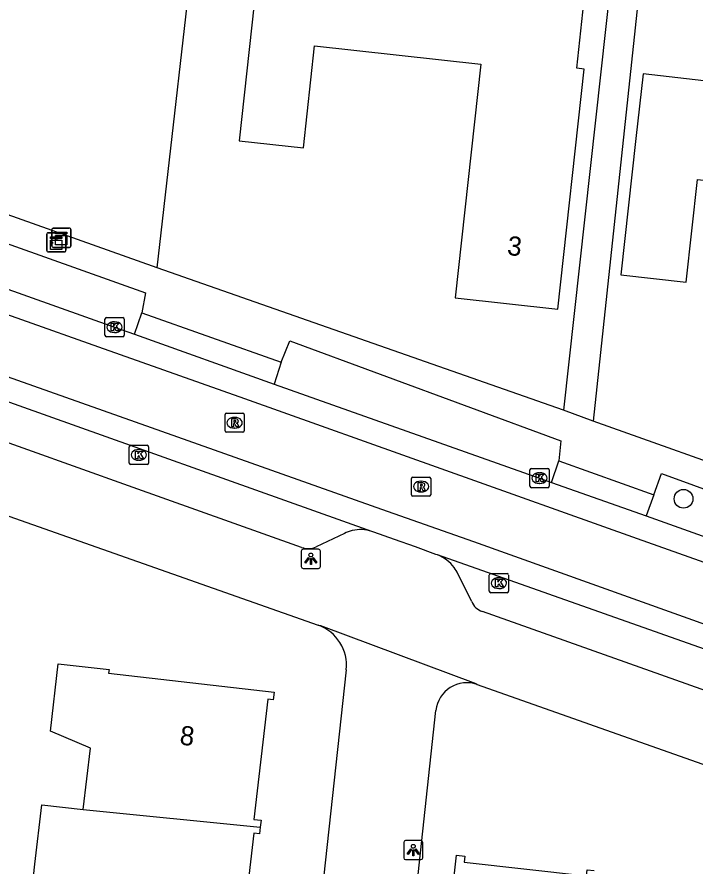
# Model space of a CAD drawing. Extents: x 162398 to 163643, y 386453 to 387397.
# Drawn here: x 162580.44 to 162615.85, y 386600.89 to 386645.28 of the extents above; entities that cross this region are included whole.
import ezdxf

# ---------------------------------------------------------------- set-up
doc = ezdxf.new("R2010")
doc.units = 0
for name, color, linetype in [('IMGEO_Boom', 7, 'Continuous'), ('IMGEO_Groenvoorziening', 7, 'Continuous'), ('IMGEO_Kast', 7, 'Continuous'), ('IMGEO_Kolk', 7, 'Continuous'), ('IMGEO_Lichtpunt', 7, 'Continuous'), ('IMGEO_Pand', 7, 'Continuous'), ('IMGEO_Pand_nummerreeks', 7, 'Continuous'), ('IMGEO_Rijbaan_lokaal_gesloten', 7, 'Continuous'), ('IMGEO_Rioolput', 7, 'Continuous'), ('IMGEO_Voetpad_open', 7, 'Continuous')]:
    doc.layers.add(name, color=color, linetype=linetype)

msp = doc.modelspace()

# ---------------------------------------------------------------- linework, layer by layer
at = {"layer": 'IMGEO_Boom'}
msp.add_circle((162615.249, 386620.12), 0.489, dxfattribs=at)
at = {"layer": 'IMGEO_Groenvoorziening'}
msp.add_lwpolyline([(162587.764, 386632.176), (162589.976, 386651.544)], dxfattribs=at)
at = {"layer": 'IMGEO_Kast'}
for p, q in [((162582.331, 386634.248), (162583.172, 386634.248)), ((162583.172, 386634.248), (162582.331, 386634.248)), ((162581.996, 386633.09), (162581.996, 386633.931)), ((162581.996, 386633.931), (162581.996, 386633.09)), ((162582.071, 386634.015), (162582.912, 386634.015)), ((162582.912, 386634.015), (162582.071, 386634.015)), ((162582.256, 386633.323), (162582.256, 386634.164)), ((162582.256, 386634.164), (162582.256, 386633.323)), ((162582.996, 386633.94), (162582.996, 386633.099)), ((162582.996, 386633.099), (162582.996, 386633.94)), ((162583.256, 386634.173), (162583.256, 386633.332)), ((162583.256, 386633.332), (162583.256, 386634.173)), ((162582.921, 386633.015), (162582.08, 386633.015)), ((162582.08, 386633.015), (162582.921, 386633.015)), ((162583.181, 386633.248), (162582.34, 386633.248)), ((162582.34, 386633.248), (162583.181, 386633.248))]:
    msp.add_line(p, q, dxfattribs=at)
for points in [[(162582.191, 386633.805), (162582.791, 386633.805), (162582.791, 386633.72), (162582.191, 386633.72), (162582.191, 386633.805)], [(162582.451, 386634.038), (162583.051, 386634.038), (162583.051, 386633.953), (162582.451, 386633.953), (162582.451, 386634.038)], [(162582.451, 386633.863), (162583.051, 386633.863), (162583.051, 386633.374), (162582.451, 386633.374), (162582.451, 386633.863)], [(162582.191, 386633.63), (162582.791, 386633.63), (162582.791, 386633.141), (162582.191, 386633.141), (162582.191, 386633.63)]]:
    msp.add_lwpolyline(points, dxfattribs=at)
for centre in [(162582.275, 386633.479), (162582.535, 386633.712)]:
    msp.add_circle(centre, 0.0377, dxfattribs=at)
for centre, start, end in [((162582.334, 386634.17), 92.4484, 184.2845), ((162582.334, 386634.17), 92.4484, 184.2845), ((162583.178, 386634.17), 2.4484, 94.2845), ((162583.178, 386634.17), 2.4484, 94.2845), ((162582.074, 386633.937), 92.4484, 184.2845), ((162582.074, 386633.937), 92.4484, 184.2845), ((162582.918, 386633.937), 2.4484, 94.2845), ((162582.918, 386633.937), 2.4484, 94.2845), ((162582.334, 386633.326), 182.4484, 274.2845), ((162582.334, 386633.326), 182.4484, 274.2845), ((162583.178, 386633.326), 272.4484, 4.2845), ((162583.178, 386633.326), 272.4484, 4.2845), ((162582.074, 386633.093), 182.4484, 274.2845), ((162582.074, 386633.093), 182.4484, 274.2845), ((162582.918, 386633.093), 272.4484, 4.2845), ((162582.918, 386633.093), 272.4484, 4.2845)]:
    msp.add_arc(centre, 0.0779, start, end, dxfattribs=at)
at = {"layer": 'IMGEO_Kolk'}
for p, q in [((162585.034, 386628.656), (162585.034, 386629.508)), ((162585.109, 386629.582), (162585.961, 386629.582)), ((162585.522, 386629.362), (162585.547, 386629.362)), ((162586.035, 386629.508), (162586.035, 386628.656)), ((162585.961, 386628.582), (162585.109, 386628.582)), ((162585.545, 386628.802), (162585.52, 386628.802)), ((162586.305, 386621.986), (162586.305, 386622.838)), ((162586.38, 386622.912), (162587.232, 386622.912)), ((162586.793, 386622.692), (162586.818, 386622.692)), ((162587.306, 386622.838), (162587.306, 386621.986)), ((162587.232, 386621.912), (162586.38, 386621.912)), ((162586.816, 386622.132), (162586.791, 386622.132)), ((162607.229, 386620.773), (162607.229, 386621.625)), ((162607.304, 386621.699), (162608.156, 386621.699)), ((162607.717, 386621.479), (162607.742, 386621.479)), ((162608.23, 386621.625), (162608.23, 386620.773)), ((162607.74, 386620.919), (162607.715, 386620.919)), ((162608.156, 386620.699), (162607.304, 386620.699)), ((162605.107, 386615.289), (162605.107, 386616.141)), ((162605.182, 386616.215), (162606.034, 386616.215)), ((162606.108, 386616.141), (162606.108, 386615.289)), ((162605.595, 386615.995), (162605.62, 386615.995)), ((162606.034, 386615.215), (162605.182, 386615.215)), ((162605.618, 386615.435), (162605.593, 386615.435))]:
    msp.add_line(p, q, dxfattribs=at)
for points in [[(162585.034, 386628.656), (162585.034, 386629.508)], [(162585.109, 386629.582), (162585.961, 386629.582)], [(162586.035, 386629.508), (162586.035, 386628.656)], [(162585.355, 386629.282), (162585.478, 386629.282), (162585.478, 386629.131), (162585.608, 386629.282), (162585.772, 386629.282), (162585.626, 386629.131), (162585.779, 386628.882), (162585.627, 386628.882), (162585.542, 386629.046), (162585.478, 386628.979), (162585.478, 386628.882), (162585.355, 386628.882), (162585.355, 386629.282)], [(162585.961, 386628.582), (162585.109, 386628.582)], [(162586.305, 386621.986), (162586.305, 386622.838)], [(162586.38, 386622.912), (162587.232, 386622.912)], [(162587.306, 386622.838), (162587.306, 386621.986)], [(162586.626, 386622.612), (162586.749, 386622.612), (162586.749, 386622.461), (162586.879, 386622.612), (162587.043, 386622.612), (162586.897, 386622.461), (162587.05, 386622.212), (162586.898, 386622.212), (162586.813, 386622.376), (162586.749, 386622.309), (162586.749, 386622.212), (162586.626, 386622.212), (162586.626, 386622.612)], [(162587.232, 386621.912), (162586.38, 386621.912)], [(162607.229, 386620.773), (162607.229, 386621.625)], [(162607.304, 386621.699), (162608.156, 386621.699)], [(162607.55, 386621.399), (162607.673, 386621.399), (162607.673, 386621.248), (162607.803, 386621.399), (162607.967, 386621.399), (162607.821, 386621.248), (162607.974, 386620.999), (162607.822, 386620.999), (162607.737, 386621.163), (162607.673, 386621.096), (162607.673, 386620.999), (162607.55, 386620.999), (162607.55, 386621.399)], [(162608.23, 386621.625), (162608.23, 386620.773)], [(162608.156, 386620.699), (162607.304, 386620.699)], [(162605.107, 386615.289), (162605.107, 386616.141)], [(162605.182, 386616.215), (162606.034, 386616.215)], [(162606.108, 386616.141), (162606.108, 386615.289)], [(162605.428, 386615.915), (162605.551, 386615.915), (162605.551, 386615.764), (162605.681, 386615.915), (162605.845, 386615.915), (162605.699, 386615.764), (162605.852, 386615.515), (162605.7, 386615.515), (162605.615, 386615.679), (162605.551, 386615.612), (162605.551, 386615.515), (162605.428, 386615.515), (162605.428, 386615.915)], [(162606.034, 386615.215), (162605.182, 386615.215)]]:
    msp.add_lwpolyline(points, dxfattribs=at)
for centre, start, end in [((162585.111, 386629.506), 91.552, 178.448), ((162585.111, 386629.506), 91.552, 178.448), ((162585.959, 386629.506), 1.552, 88.448), ((162585.959, 386629.506), 1.552, 88.448), ((162585.111, 386628.658), 181.552, 268.448), ((162585.111, 386628.658), 181.552, 268.448), ((162585.959, 386628.658), 271.552, 358.448), ((162585.959, 386628.658), 271.552, 358.448), ((162586.382, 386622.836), 91.552, 178.448), ((162586.382, 386622.836), 91.552, 178.448), ((162587.23, 386622.836), 1.552, 88.448), ((162587.23, 386622.836), 1.552, 88.448), ((162586.382, 386621.988), 181.552, 268.448), ((162586.382, 386621.988), 181.552, 268.448), ((162587.23, 386621.988), 271.552, 358.448), ((162587.23, 386621.988), 271.552, 358.448), ((162607.306, 386621.623), 91.552, 178.448), ((162607.306, 386621.623), 91.552, 178.448), ((162608.154, 386621.623), 1.552, 88.448), ((162608.154, 386621.623), 1.552, 88.448), ((162607.306, 386620.775), 181.552, 268.448), ((162607.306, 386620.775), 181.552, 268.448), ((162608.154, 386620.775), 271.552, 358.448), ((162608.154, 386620.775), 271.552, 358.448), ((162605.184, 386616.139), 91.552, 178.448), ((162605.184, 386616.139), 91.552, 178.448), ((162606.032, 386616.139), 1.552, 88.448), ((162606.032, 386616.139), 1.552, 88.448), ((162605.184, 386615.291), 181.552, 268.448), ((162605.184, 386615.291), 181.552, 268.448), ((162606.032, 386615.291), 271.552, 358.448), ((162606.032, 386615.291), 271.552, 358.448)]:
    msp.add_arc(centre, 0.0765, start, end, dxfattribs=at)
for centre, major_axis, ratio, start_param, end_param in [((162585.521, 386629.082), (-0.387, 0.002), 0.722429, 4.712389, 7.853982), ((162585.546, 386629.082), (-0.39, 0.002), 0.717154, 1.570796, 4.712389), ((162586.792, 386622.412), (-0.387, 0.002), 0.722429, 4.712389, 7.853982), ((162586.817, 386622.412), (-0.39, 0.002), 0.717154, 1.570796, 4.712389), ((162607.716, 386621.199), (-0.387, 0.002), 0.722429, 4.712389, 7.853982), ((162607.741, 386621.199), (-0.39, 0.002), 0.717154, 1.570796, 4.712389), ((162605.594, 386615.715), (-0.387, 0.002), 0.722429, 4.712389, 7.853982), ((162605.619, 386615.715), (-0.39, 0.002), 0.717154, 1.570796, 4.712389)]:
    msp.add_ellipse(centre, major_axis=major_axis, ratio=ratio, start_param=start_param, end_param=end_param, dxfattribs=at)
at = {"layer": 'IMGEO_Lichtpunt'}
for p, q in [((162595.29, 386617.388), (162595.29, 386616.581)), ((162595.29, 386617.388), (162595.29, 386616.581)), ((162596.192, 386617.483), (162595.384, 386617.483)), ((162596.192, 386617.483), (162595.384, 386617.483)), ((162596.286, 386616.581), (162596.286, 386617.388)), ((162596.286, 386616.581), (162596.286, 386617.388)), ((162595.384, 386616.487), (162596.192, 386616.487)), ((162595.384, 386616.487), (162596.192, 386616.487)), ((162601.539, 386602.274), (162600.731, 386602.274)), ((162601.539, 386602.274), (162600.731, 386602.274)), ((162600.637, 386602.179), (162600.637, 386601.372)), ((162600.637, 386602.179), (162600.637, 386601.372)), ((162601.633, 386601.372), (162601.633, 386602.179)), ((162601.633, 386601.372), (162601.633, 386602.179)), ((162600.731, 386601.278), (162601.539, 386601.278)), ((162600.731, 386601.278), (162601.539, 386601.278))]:
    msp.add_line(p, q, dxfattribs=at)
for points in [[(162595.664, 386617.052), (162595.703, 386617.024), (162595.515, 386616.762), (162595.477, 386616.789), (162595.664, 386617.052)], [(162595.766, 386617.004), (162595.813, 386617.004), (162595.813, 386616.682), (162595.766, 386616.682), (162595.766, 386617.004)], [(162595.876, 386617.024), (162595.914, 386617.051), (162596.101, 386616.789), (162596.062, 386616.761), (162595.876, 386617.024)], [(162601.011, 386601.843), (162601.05, 386601.815), (162600.862, 386601.553), (162600.824, 386601.58), (162601.011, 386601.843)], [(162601.223, 386601.815), (162601.261, 386601.842), (162601.448, 386601.58), (162601.409, 386601.552), (162601.223, 386601.815)], [(162601.113, 386601.795), (162601.16, 386601.795), (162601.16, 386601.473), (162601.113, 386601.473), (162601.113, 386601.795)]]:
    msp.add_lwpolyline(points, dxfattribs=at)
for centre in [(162595.789, 386617.186), (162601.136, 386601.977)]:
    msp.add_circle(centre, 0.0994, dxfattribs=at)
for centre, start, end in [((162595.384, 386617.388), 90, 180), ((162595.384, 386617.388), 90, 180), ((162596.192, 386617.388), 0, 90), ((162596.192, 386617.388), 0, 90), ((162595.384, 386616.581), 180, 270), ((162595.384, 386616.581), 180, 270), ((162596.192, 386616.581), 270, 0), ((162596.192, 386616.581), 270, 360), ((162600.731, 386602.179), 90, 180), ((162600.731, 386602.179), 90, 180), ((162601.539, 386602.179), 0, 90), ((162601.539, 386602.179), 0, 90), ((162600.731, 386601.372), 180, 270), ((162600.731, 386601.372), 180, 270), ((162601.539, 386601.372), 270, 0), ((162601.539, 386601.372), 270, 360)]:
    msp.add_arc(centre, 0.0946, start, end, dxfattribs=at)
at = {"layer": 'IMGEO_Pand'}
for points in [[(162601.831, 386648.402), (162596.304, 386649.01), (162593.2, 386649.351), (162592.828, 386645.969), (162592.041, 386638.819), (162595.395, 386638.449), (162595.981, 386643.772), (162604.668, 386642.815), (162603.325, 386630.619), (162608.688, 386630.029), (162610.068, 386642.562), (162609.67, 386642.605), (162610.208, 386647.493)], [(162625.201, 386640.975), (162616.314, 386641.952), (162613.136, 386642.302), (162612.765, 386638.93), (162611.982, 386631.813), (162615.386, 386631.438), (162615.976, 386636.794), (162624.645, 386635.839), (162623.285, 386623.487), (162628.588, 386622.903), (162629.964, 386635.399), (162629.51, 386635.449), (162630.059, 386640.442)], [(162583.906, 386603.898), (162584.272, 386607.098), (162582.185, 386607.992), (162582.587, 386611.505), (162585.25, 386611.2), (162585.229, 386611.015), (162593.871, 386610.025), (162593.825, 386609.624), (162593.533, 386609.658), (162592.813, 386603.377), (162593.189, 386603.334), (162593.149, 386602.978)], [(162580.97, 386597.316), (162581.379, 386601.045), (162581.734, 386604.147), (162583.906, 386603.898)], [(162583.906, 386603.898), (162593.149, 386602.978)], [(162593.149, 386602.978), (162593.108, 386602.621), (162592.802, 386602.656), (162592.083, 386596.383), (162592.447, 386596.342), (162592.409, 386596.012)], [(162609.336, 386591.165), (162609.127, 386591.188), (162609.166, 386591.536), (162606.433, 386591.841), (162605.086, 386588.936), (162601.493, 386589.817), (162600.599, 386589.916), (162601.336, 386596.515), (162602.826, 386596.349), (162603.402, 386601.507), (162603.837, 386601.458), (162603.802, 386601.141), (162610.188, 386600.428), (162610.224, 386600.747), (162610.578, 386600.708)]]:
    msp.add_lwpolyline(points, dxfattribs=at)
at = {"layer": 'IMGEO_Rijbaan_lokaal_gesloten'}
for points in [[(162548.628, 386642.19), (162552.639, 386640.768), (162569.093, 386634.931), (162585.535, 386629.082), (162586.579, 386628.708)], [(162647.194, 386605.99), (162641.405, 386607.888), (162633.104, 386610.835), (162612.847, 386618.032), (162592.338, 386625.34), (162584.71, 386628.039), (162568.609, 386633.752), (162548.204, 386641)], [(162547.159, 386638.157), (162567.328, 386630.965), (162587.442, 386623.845), (162599.474, 386619.574), (162604.276, 386617.886), (162625.443, 386610.322), (162636.32, 386606.456), (162640.402, 386605.025), (162644.832, 386603.568), (162646.48, 386603.055)], [(162586.579, 386628.708), (162593.88, 386626.111)], [(162593.88, 386626.111), (162607.73, 386621.199), (162608.356, 386620.966)], [(162598.974, 386618.418), (162579.029, 386625.507)], [(162608.356, 386620.966), (162613.293, 386619.229)], [(162613.293, 386619.229), (162627.057, 386614.318), (162627.161, 386614.281)], [(162602.395, 386617.191), (162602.318, 386617.218), (162601.252, 386617.606), (162600.155, 386617.992), (162599.078, 386618.381), (162598.974, 386618.418)], [(162625.654, 386608.978), (162602.395, 386617.191)]]:
    msp.add_lwpolyline(points, dxfattribs=at)
at = {"layer": 'IMGEO_Rioolput'}
for p, q in [((162591.305, 386623.665), (162591.305, 386624.517)), ((162591.38, 386624.591), (162592.232, 386624.591)), ((162592.306, 386624.517), (162592.306, 386623.665)), ((162591.793, 386624.371), (162591.818, 386624.371)), ((162592.232, 386623.591), (162591.38, 386623.591)), ((162591.816, 386623.811), (162591.791, 386623.811)), ((162601.044, 386620.33), (162601.044, 386621.182)), ((162601.119, 386621.256), (162601.971, 386621.256)), ((162601.532, 386621.036), (162601.557, 386621.036)), ((162602.045, 386621.182), (162602.045, 386620.33)), ((162601.555, 386620.476), (162601.53, 386620.476)), ((162601.971, 386620.256), (162601.119, 386620.256))]:
    msp.add_line(p, q, dxfattribs=at)
for points in [[(162591.305, 386623.665), (162591.305, 386624.517)], [(162591.38, 386624.591), (162592.232, 386624.591)], [(162592.306, 386624.517), (162592.306, 386623.665)], [(162591.894, 386624.289), (162591.642, 386624.291), (162591.642, 386623.891)], [(162591.642, 386623.891), (162591.766, 386623.891), (162591.766, 386624.053), (162591.777, 386624.053)], [(162591.82, 386624.21), (162591.766, 386624.21), (162591.766, 386624.129)], [(162591.766, 386624.129), (162591.818, 386624.129)], [(162591.824, 386624.024), (162591.895, 386623.891), (162592.035, 386623.891), (162591.97, 386624.017)], [(162592.232, 386623.591), (162591.38, 386623.591)], [(162601.044, 386620.33), (162601.044, 386621.182)], [(162601.119, 386621.256), (162601.971, 386621.256)], [(162601.633, 386620.954), (162601.381, 386620.956), (162601.381, 386620.556)], [(162602.045, 386621.182), (162602.045, 386620.33)], [(162601.381, 386620.556), (162601.505, 386620.556), (162601.505, 386620.718), (162601.516, 386620.718)], [(162601.559, 386620.875), (162601.505, 386620.875), (162601.505, 386620.794)], [(162601.505, 386620.794), (162601.557, 386620.794)], [(162601.563, 386620.689), (162601.634, 386620.556), (162601.774, 386620.556), (162601.709, 386620.682)], [(162601.971, 386620.256), (162601.119, 386620.256)]]:
    msp.add_lwpolyline(points, dxfattribs=at)
for centre, radius, start, end in [((162591.382, 386624.515), 0.0765, 91.552, 178.448), ((162591.382, 386624.515), 0.0765, 91.552, 178.448), ((162592.23, 386624.515), 0.0765, 1.552, 88.448), ((162592.23, 386624.515), 0.0765, 1.552, 88.448), ((162591.776, 386624), 0.0533, 26.0293, 88.6989), ((162591.802, 386624.318), 0.19, 274.7715, 282.9687), ((162591.826, 386624.114), 0.0964, 77.0061, 93.1865), ((162591.84, 386624.171), 0.0378, 276.6634, 79.6772), ((162591.893, 386624.179), 0.109, 350.3612, 89.416), ((162591.891, 386624.179), 0.112, 277.5842, 350.9817), ((162591.875, 386623.964), 0.108, 29.5134, 73.7905), ((162591.382, 386623.667), 0.0765, 181.552, 268.448), ((162591.382, 386623.667), 0.0765, 181.552, 268.448), ((162592.23, 386623.667), 0.0765, 271.552, 358.448), ((162592.23, 386623.667), 0.0765, 271.552, 358.448), ((162601.121, 386621.18), 0.0765, 91.552, 178.448), ((162601.121, 386621.18), 0.0765, 91.552, 178.448), ((162601.632, 386620.844), 0.109, 350.3612, 89.416), ((162601.969, 386621.18), 0.0765, 1.552, 88.448), ((162601.969, 386621.18), 0.0765, 1.552, 88.448), ((162601.515, 386620.665), 0.0533, 26.0293, 88.6989), ((162601.541, 386620.983), 0.19, 274.7715, 282.9687), ((162601.565, 386620.779), 0.0964, 77.0061, 93.1865), ((162601.579, 386620.836), 0.0378, 276.6634, 79.6772), ((162601.63, 386620.844), 0.112, 277.5842, 350.9817), ((162601.614, 386620.629), 0.108, 29.5134, 73.7905), ((162601.121, 386620.332), 0.0765, 181.552, 268.448), ((162601.121, 386620.332), 0.0765, 181.552, 268.448), ((162601.969, 386620.332), 0.0765, 271.552, 358.448), ((162601.969, 386620.332), 0.0765, 271.552, 358.448)]:
    msp.add_arc(centre, radius, start, end, dxfattribs=at)
for centre, major_axis, ratio, start_param, end_param in [((162591.792, 386624.091), (-0.387, 0.002), 0.722429, 4.712389, 7.853982), ((162591.817, 386624.091), (-0.39, 0.002), 0.717154, 1.570796, 4.712389), ((162601.531, 386620.756), (-0.387, 0.002), 0.722429, 4.712389, 7.853982), ((162601.556, 386620.756), (-0.39, 0.002), 0.717154, 1.570796, 4.712389)]:
    msp.add_ellipse(centre, major_axis=major_axis, ratio=ratio, start_param=start_param, end_param=end_param, dxfattribs=at)
at = {"layer": 'IMGEO_Voetpad_open'}
for points in [[(162614.719, 386663.466), (162610.524, 386624.181)], [(162612.099, 386659.995), (162612.855, 386659.948), (162608.983, 386624.745)], [(162587.764, 386632.176), (162550.979, 386645.25)], [(162548.316, 386642.319), (162549.95, 386644.138), (162569.801, 386637.061), (162587.153, 386630.88), (162586.965, 386629.834)], [(162608.983, 386624.745), (162587.764, 386632.176)], [(162586.579, 386628.708), (162586.965, 386629.834)], [(162586.965, 386629.834), (162594.234, 386627.259)], [(162594.234, 386627.259), (162594.697, 386628.36), (162608.836, 386623.148), (162608.745, 386622.1)], [(162594.234, 386627.259), (162593.88, 386626.111)], [(162610.524, 386624.181), (162608.983, 386624.745)], [(162628.73, 386617.707), (162610.524, 386624.181)], [(162595.304, 386617.585), (162586.273, 386620.802), (162578.358, 386623.624)], [(162608.356, 386620.966), (162608.745, 386622.1)], [(162608.745, 386622.1), (162613.692, 386620.329)], [(162573.621, 386621.455), (162596.17, 386613.523)], [(162613.692, 386620.329), (162614.096, 386621.447), (162627.851, 386616.434), (162627.564, 386615.41)], [(162613.692, 386620.329), (162613.293, 386619.229)], [(162597.541, 386618.309), (162596.073, 386617.615)], [(162604.187, 386614.752), (162603.471, 386616.194)], [(162624.944, 386607.063), (162604.746, 386614.239)], [(162596.17, 386613.523), (162596.286, 386613.509), (162604.405, 386610.482), (162604.476, 386610.426)], [(162597.635, 386611.189), (162595.004, 386587.03), (162593.535, 386587.193)], [(162604.476, 386610.426), (162627.944, 386602.131)], [(162599.162, 386579.822), (162602.317, 386609.066)]]:
    msp.add_lwpolyline(points, dxfattribs=at)
for centre, radius, start, end in [((162598.37, 386616.67), 1.836, 103.2103, 116.8234), ((162598.391, 386616.611), 1.899, 72.1056, 103.4204), ((162595.654, 386618.489), 0.97, 248.8521, 295.6161), ((162601.708, 386615.37), 1.947, 36.5913, 69.3348), ((162601.78, 386615.415), 1.862, 24.7365, 36.7889), ((162605.001, 386615.078), 0.877, 201.8384, 253.0758), ((162595.422, 386611.426), 2.226, 353.8773, 70.3539), ((162603.935, 386608.892), 1.627, 70.5684, 173.847)]:
    msp.add_arc(centre, radius, start, end, dxfattribs=at)

# ---------------------------------------------------------------- texts
at = {"layer": 'IMGEO_Pand_nummerreeks'}
for s, rotation, p in [('3', 353.722, (162606.008, 386632.859)), ('8', 353.4649, (162588.907, 386607.292))]:
    msp.add_text(s, height=1, rotation=rotation, dxfattribs=at).set_placement(p)

doc.saveas('drawing.dxf')
